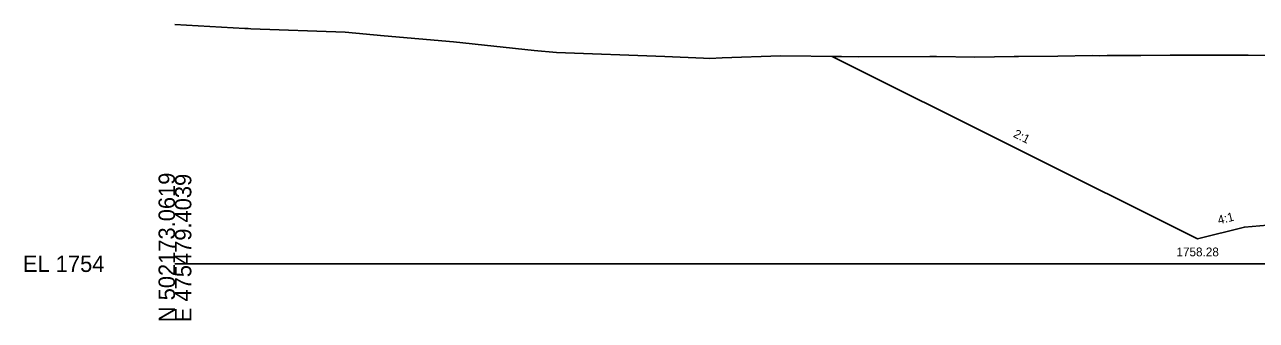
# Model space of a CAD drawing. Extents: x -26 to 1803, y -10 to 9558.
# Drawn here: x -25.7 to 184.8, y 6990.3 to 7040.9 of the extents above; entities that cross this region are included whole.
import ezdxf

# ---------------------------------------------------------------- set-up
doc = ezdxf.new("R2010")
doc.units = 0
for name, color, linetype in [('Exist Cross Section Cell', 7, 'Continuous'), ('Exist XS Ground Line', 7, 'Continuous'), ('Prop XS Ditch Slope Text', 7, 'Continuous'), ('Prop XS Ditch Standard Text', 7, 'Continuous'), ('Prop XS Dump Level', 7, 'Continuous'), ('Prop XS Earthwork Shape', 7, 'Continuous'), ('Prop XS Finish Grade Earthwork', 7, 'Continuous'), ('Prop XS Hydro Typical Ditch Data', 7, 'Continuous'), ('Prop XS Side Slope Text', 7, 'Continuous')]:
    doc.layers.add(name, color=color, linetype=linetype)

msp = doc.modelspace()

# ---------------------------------------------------------------- linework, layer by layer
at = {"layer": 'Exist Cross Section Cell'}
msp.add_line((0, 7000), (200, 7000), dxfattribs=at)
at = {"layer": 'Exist XS Ground Line'}
msp.add_lwpolyline([(0, 7040.95), (11.94, 7040.29), (12.51, 7040.26), (12.96, 7040.24), (29.11, 7039.66), (35.77, 7039.05), (47.62, 7037.98), (61.42, 7036.53), (65.21, 7036.18), (83.74, 7035.46), (90.31, 7035.19), (91.4, 7035.17), (93.55, 7035.23), (103.49, 7035.62), (113.9, 7035.48), (116.81, 7035.45), (129.04, 7035.47), (130.14, 7035.47), (136.71, 7035.39), (143.46, 7035.49), (143.8, 7035.49), (144.18, 7035.5), (150.88, 7035.57), (156.79, 7035.63), (157.97, 7035.62), (159.31, 7035.63), (165.06, 7035.63), (170.11, 7035.7), (174.45, 7035.72), (183.44, 7035.72), (189.59, 7035.67)], dxfattribs=at)
at = {"layer": 'Prop XS Earthwork Shape'}
msp.add_lwpolyline([(186.72, 7006.59), (182.79, 7006.28), (174.79, 7004.28), (112.32, 7035.5), (113.9, 7035.48), (116.81, 7035.45), (129.04, 7035.47), (130.14, 7035.47), (136.71, 7035.39), (143.46, 7035.49), (143.8, 7035.49), (144.18, 7035.5), (150.88, 7035.57), (156.79, 7035.63), (157.97, 7035.62), (159.31, 7035.63), (165.06, 7035.63), (170.11, 7035.7), (174.45, 7035.72), (183.44, 7035.72), (189.59, 7035.67)], dxfattribs=at)
at = {"layer": 'Prop XS Finish Grade Earthwork'}
for p, q in [((174.79, 7004.28), (112.32, 7035.5)), ((182.79, 7006.28), (174.79, 7004.28)), ((186.72, 7006.59), (182.79, 7006.28))]:
    msp.add_line(p, q, dxfattribs=at)
at = {"layer": 'Prop XS Hydro Typical Ditch Data'}
for p, q in [((174.79, 7004.28), (112.32, 7035.5)), ((182.79, 7006.28), (174.79, 7004.28))]:
    msp.add_line(p, q, dxfattribs=at)

# ---------------------------------------------------------------- texts
at = {"layer": 'Exist Cross Section Cell'}
for s, p in [('N 502173.0619', (0, 6990)), ('E 475479.4039', (2.8, 6990))]:
    msp.add_text(s, height=2.8, rotation=90, dxfattribs=at).set_placement(p)
msp.add_text('EL 1754', height=2.8, dxfattribs=at).set_placement((-26, 6998.6))
at = {"layer": 'Prop XS Ditch Slope Text'}
msp.add_text('4:1', height=1.5, rotation=14.0307, dxfattribs=at).set_placement((178.42, 7006.73))
at = {"layer": 'Prop XS Ditch Standard Text'}
msp.add_text('1758.28', height=1.5, dxfattribs=at).set_placement((171.17, 7001.28))
at = {"layer": 'Prop XS Dump Level'}
msp.add_text('Case1', height=0.04, dxfattribs=at).set_placement((182.79, 7006.24))
at = {"layer": 'Prop XS Side Slope Text'}
msp.add_text('2:1', height=1.5, rotation=333.4444, dxfattribs=at).set_placement((143.16, 7021.76))

doc.saveas('drawing.dxf')
